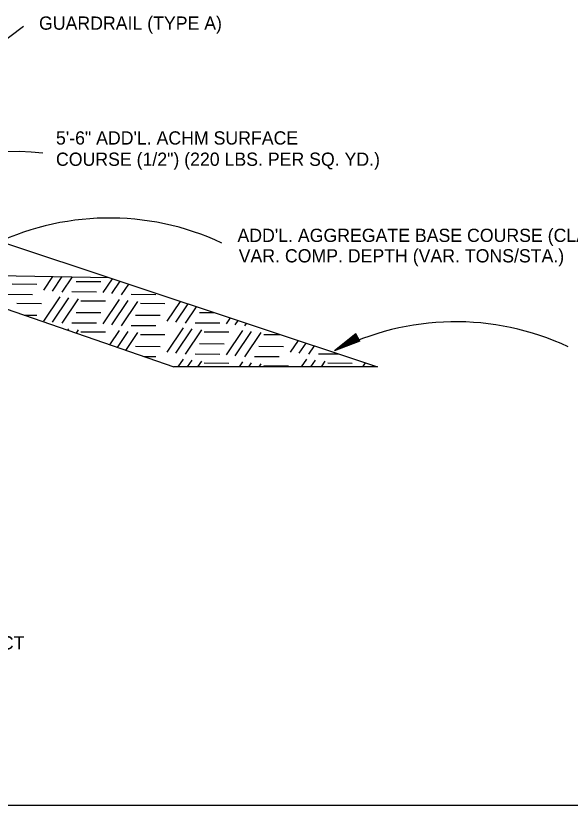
# Model space of a CAD drawing. Extents: x 1931522 to 1935523, y 600380 to 605075.
# Drawn here: x 1933498.3 to 1933752.7, y 604532.1 to 604894.2 of the extents above; entities that cross this region are included whole.
import ezdxf

# ---------------------------------------------------------------- set-up
doc = ezdxf.new("R2010")
doc.units = 0
doc.layers.add('Default', color=7, linetype='Continuous')
doc.layers.add('R_Border', color=7, linetype='Continuous')

msp = doc.modelspace()

# ---------------------------------------------------------------- linework, layer by layer
at = {"layer": 'Default'}
for p, q in [((1933432.53, 604837.14), (1933501.84, 604889.53)), ((1933483.61, 604793.23), (1933664.23, 604733.18)), ((1933147.68, 604781.96), (1933541.06, 604774.13)), ((1933446.72, 604776.01), (1933570.77, 604733.18)), ((1933654.36, 604748.26), (1933644.62, 604740.49)), ((1933654.53, 604747.97), (1933646.41, 604741.5)), ((1933654.68, 604747.7), (1933648.23, 604742.58)), ((1933654.83, 604747.45), (1933650, 604743.61)), ((1933654.97, 604747.16), (1933651.8, 604744.65)), ((1933655.15, 604746.89), (1933653.62, 604745.68)), ((1933656.23, 604745.04), (1933654.36, 604748.26)), ((1933656.23, 604745.04), (1933644.62, 604740.49)), ((1933656.06, 604745.31), (1933646.41, 604741.5)), ((1933655.88, 604745.58), (1933648.23, 604742.58)), ((1933655.74, 604745.83), (1933650, 604743.61)), ((1933655.59, 604746.1), (1933651.8, 604744.65)), ((1933655.44, 604746.39), (1933653.62, 604745.68)), ((1933664.23, 604733.18), (1933570.77, 604733.18)), ((1933663.7, 604733.18), (1933663.84, 604733.31)), ((1933664.14, 604733.21), (1933664.17, 604733.18))]:
    msp.add_line(p, q, dxfattribs=at)
for centre in [(1933541.23, 604679.75), (1933700.13, 604632.16)]:
    msp.add_arc(centre, 121.72, 64.8876, 117.1378, dxfattribs=at)
msp.add_ellipse((1933505.82, 604791.35), major_axis=(-60.8, 7.42), ratio=0.655798, start_param=4.712389, end_param=6.093533, dxfattribs=at)
at = {"layer": 'R_Border'}
for p, q in [((1933511.12, 604768.43), (1933515.32, 604774.65)), ((1933515.11, 604767.96), (1933519.56, 604774.56)), ((1933519.56, 604767.5), (1933524.26, 604774.47)), ((1933525.95, 604772.41), (1933537.26, 604772.32)), ((1933538.38, 604767.22), (1933542.67, 604773.59)), ((1933542.36, 604766.76), (1933546.19, 604772.42)), ((1933496.59, 604771.21), (1933507.9, 604771.12)), ((1933546.81, 604766.29), (1933550.08, 604771.13)), ((1933494.64, 604766.48), (1933505.95, 604766.39)), ((1933511.12, 604754.16), (1933518.63, 604765.29)), ((1933515.11, 604753.7), (1933522.62, 604764.83)), ((1933524.01, 604767.68), (1933535.32, 604767.59)), ((1933551.26, 604766.48), (1933562.57, 604766.39)), ((1933498.81, 604762.33), (1933510.12, 604762.23)), ((1933519.56, 604753.24), (1933527.07, 604764.37)), ((1933528.18, 604763.53), (1933539.49, 604763.44)), ((1933538.38, 604752.96), (1933545.88, 604764.09)), ((1933542.36, 604752.5), (1933549.87, 604763.62)), ((1933546.81, 604752.03), (1933554.32, 604763.16)), ((1933555.43, 604762.33), (1933566.74, 604762.23)), ((1933567.74, 604754.16), (1933573.86, 604763.23)), ((1933571.73, 604753.7), (1933577.37, 604762.06)), ((1933525.95, 604758.15), (1933537.26, 604758.06)), ((1933576.18, 604753.24), (1933581.26, 604760.76)), ((1933582.57, 604758.15), (1933589.28, 604758.1)), ((1933502.06, 604756.9), (1933507.9, 604756.85)), ((1933553.21, 604756.95), (1933564.52, 604756.85)), ((1933595, 604752.96), (1933596.78, 604755.6)), ((1933598.98, 604752.5), (1933600.29, 604754.44)), ((1933522.2, 604749.95), (1933522.62, 604750.57)), ((1933524.01, 604753.42), (1933535.32, 604753.33)), ((1933526.06, 604748.62), (1933527.07, 604750.1)), ((1933551.26, 604752.22), (1933562.57, 604752.12)), ((1933567.74, 604739.9), (1933575.25, 604751.03)), ((1933571.73, 604739.44), (1933579.24, 604750.57)), ((1933576.18, 604738.98), (1933583.69, 604750.1)), ((1933580.63, 604753.42), (1933591.94, 604753.33)), ((1933603.43, 604752.03), (1933604.18, 604753.14)), ((1933528.18, 604749.27), (1933539.49, 604749.18)), ((1933541.48, 604743.3), (1933545.88, 604749.83)), ((1933544.97, 604742.09), (1933549.87, 604749.36)), ((1933548.83, 604740.76), (1933554.32, 604748.9)), ((1933555.43, 604748.06), (1933566.74, 604747.97)), ((1933584.8, 604749.27), (1933596.11, 604749.18)), ((1933595, 604738.7), (1933602.51, 604749.83)), ((1933598.98, 604738.23), (1933606.49, 604749.36)), ((1933603.43, 604737.77), (1933610.94, 604748.9)), ((1933612.05, 604748.06), (1933619.65, 604748)), ((1933582.57, 604743.89), (1933593.88, 604743.8)), ((1933624.36, 604739.9), (1933627.96, 604745.24)), ((1933628.35, 604739.44), (1933631.47, 604744.07)), ((1933553.21, 604742.69), (1933564.52, 604742.59)), ((1933609.83, 604742.69), (1933621.14, 604742.59)), ((1933632.8, 604738.98), (1933635.36, 604742.78)), ((1933557.08, 604737.91), (1933562.57, 604737.86)), ((1933572.83, 604733.18), (1933575.25, 604736.77)), ((1933577.13, 604733.18), (1933579.24, 604736.31)), ((1933580.63, 604739.16), (1933591.94, 604739.07)), ((1933581.89, 604733.18), (1933583.69, 604735.84)), ((1933600.9, 604733.18), (1933602.51, 604735.56)), ((1933607.88, 604737.96), (1933619.19, 604737.86)), ((1933629.45, 604733.18), (1933631.87, 604736.77)), ((1933633.75, 604733.18), (1933635.86, 604736.31)), ((1933637.25, 604739.16), (1933646.47, 604739.09)), ((1933638.51, 604733.18), (1933640.31, 604735.84)), ((1933584.8, 604735.01), (1933596.11, 604734.91)), ((1933605.2, 604733.18), (1933606.49, 604735.1)), ((1933609.96, 604733.18), (1933610.94, 604734.64)), ((1933612.05, 604733.8), (1933623.36, 604733.71)), ((1933641.42, 604735.01), (1933652.73, 604734.91)), ((1933657.52, 604733.18), (1933658.75, 604735)), ((1933661.82, 604733.18), (1933662.26, 604733.84)), ((1932766.98, 604532.1), (1934247.02, 604532.1))]:
    msp.add_line(p, q, dxfattribs=at)

# ---------------------------------------------------------------- texts
at = {"layer": 'Default'}
for s, p in [('GUARDRAIL (TYPE A)', (1933508.93, 604887.83)), ('5\'-6" ADD\'L. ACHM SURFACE ', (1933516.71, 604835.16)), ('COURSE (1/2") (220 LBS. PER SQ. YD.)', (1933516.71, 604825.4)), ("ADD'L. AGGREGATE BASE COURSE (CLASS 7)", (1933600.01, 604790.48)), ('VAR. COMP. DEPTH (VAR. TONS/STA.)', (1933600.57, 604781.09)), ('       MATCH THE SLOPES AND GRADES OF THE MAIN LANE SHOULDERS.  CONSTRUCT', (1933159.65, 604603.55))]:
    msp.add_text(s, height=6.075, rotation=360, dxfattribs=at).set_placement(p)

doc.saveas('drawing.dxf')
